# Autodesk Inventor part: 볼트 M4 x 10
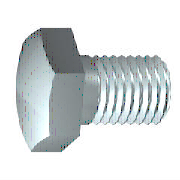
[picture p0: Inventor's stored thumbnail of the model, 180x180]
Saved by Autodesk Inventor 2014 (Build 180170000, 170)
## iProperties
Created: 2012-02
Part Number: 볼트 M4 x 10
Material: 스테인리스강
Description: 6각 머리 나사
Document SubType Name: Modeling
Standard: ISO 4017
Designer: mduedu
Standard Revision: Third edition 1999-08-15
Standards Organization: ISO
Language: ko-KR
Size Designation: M4 x 10
Categories: <MemberInstance><Categories><Category DisplayName="조임쇠" InternalName="e4da775c-781d-43d5-af7c-5136215cf5a6" Mnemonic="FSTN"><Category DisplayName="볼트" InternalN
Density: 8.08 g/cm^3
Appearance: 기본값
IsCustomPart: 0
Author: mduedu
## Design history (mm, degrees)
sketch "스케치1"
  geometry: L1 (0, 3.015)-(0, 2); L2 (2.1, 2)-(10, 2); L3 (10, 2)-(10, 0); L4 (10, 0)-(-0.4, 0); L5 (-2.48, 0)-(12.08, 0) reference; L6 (-0.4, 0)-(-0.4, 3.015); L7 (-0.4, 3.015)-(0, 3.015); L8 (2.1, 2)-(1.67, 2); L9 (1.67, 2)-(0, 2); L10 (0, -0.603)-(0, 3.618) reference
  constraints: 16 end point, 2 collinear, 2 perpendicular, 1 parallel
  dimensions: "d0" = 10 distance between parallel lines of L3 L1 (= NLG); "d1" = 7.9 distance from line of L2.start L3 (= GEL); "d2" = 4 diameter of L2 L4 (= GD); "d9" = 0.4001 distance between parallel lines of L6 L1 (computed from SD); "d10" = 6.03 diameter of L7 L4 (= SD2); "d13" = 0.42952 distance of L2.start L8.end (computed from GAL); "d14" = 4 diameter of L9 L4 (= BDM)
revolve "본체" sketch "스케치1" stored, may be unused: angle "d12" = 90 deg
sketch "스케치2"
  geometry: L1 (0, 4.041)-(3.5, 2.021); L2 (3.5, 2.021)-(3.5, -2.021); L3 (3.5, -2.021)-(0, -4.041); L4 (0, -4.041)-(-3.5, -2.021); L5 (-3.5, -2.021)-(-3.5, 2.021); L6 (-3.5, 2.021)-(0, 4.041); 2 further points
  constraints: 12 end point, 1 coincident, 1 vertical, 11 other
  dimensions: "d11" = 7 distance between parallel lines of L5 L2 (= SW)
extrude "머리" join sketch "스케치2" distance "d3" = 2.4 (= KOH - SD); taper "d4" = 0 deg
sketch "스케치4"
  geometry: L1 (-2.8, 3.5)-(-2.8, 4.041); L2 (-2.8, 4.041)-(-2.487, 4.041); L3 (-2.487, 4.041)-(-2.8, 3.5); L4 (-3.28, 0)-(0.08, 0) reference; L5 (-0.4, 4.041)-(-2.8, 4.041) reference; L6 (-2.8, 2.021)-(-2.8, 4.041) reference
  constraints: 6 end point, 2 collinear, 1 perpendicular, 1 vertical
  dimensions: "d5" = 30 deg angle of L3 L1 (= ANG1); "d19" = 7 diameter of L1.start L4 (= SW0)
revolve "모따기1" sketch "스케치4" stored, may be unused: angle "d21" = 90 deg
workplane "Work Plane1"
body "Solid1"
feature "스레드" dims "d15" = 7.9 (= GEL), "d16" = 0
chamfer "모따기2" distance "d6" = 0.42941 (= -0.5 x SPD + 0.5 x GD); stored, may be unused: second distance "d7" = 0.42952 (computed from GUL), angle "d55" = 45 deg
other parameters: "NLG" = 10 [user parameter; used in 1 equation term], "GD" = 4 (= NND) [user parameter; used in 2 equation terms], "BDM" = 4 (= NND) [user parameter; used in 1 equation term], "KOH" = 2.8 [user parameter; used in 1 equation term], "GEL" = 7.9 [user parameter; used in 2 equation terms], "SW" = 7 [user parameter; used in 2 equation terms], "SW0" = 7 (= SW) [user parameter; used in 1 equation term], "SPD" = 3.14117 (= NND - 1.2269 x PTC) [user parameter; used in 1 equation term], "SD2" = 6.03 [user parameter; used in 2 equation terms], "SD" = 0.4 [user parameter; used in 2 equation terms], "ANG1" = 30 deg [user parameter; used in 1 equation term], "GAL" = 0.42941 (= 0.61345 x PTC) [user parameter; used in 1 equation term], "GUL" = 0.42941 (= 0.61345 x PTC) [user parameter; used in 1 equation term], "d8" = 0, "RR" = 0.2 [user parameter], "d57" = 0, "d58" = 0, "TPU" = 14.28571 (computed from PTC) [user parameter], "GD1" = 3.14117 (= THREADDIA - 1.2269 x PTC) [user parameter], "THREADDIA" = 4 [user parameter; used in 1 equation term], "SDH" = 6.03 (= SD2) [user parameter], "SDHG" = 2.1 [user parameter], "TOA" = 30 deg [user parameter], "PTC" = 0.7 [user parameter; used in 5 equation terms], "NND" = 4 [user parameter; used in 3 equation terms], "E0" = 8.085 [user parameter]
